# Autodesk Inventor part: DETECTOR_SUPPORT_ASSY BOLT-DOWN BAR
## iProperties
Shininess: 64.0
Length Units: 11272
Angle Units: 11279
Time Units: 11290
Mass Units: 11286
Length Display Precision: 3
Angle Display Precision: 2
Compacted: True
Part Number: DETECTOR_SUPPORT_ASSY BOLT-DOWN BAR
Document SubType Name: Modeling
Created: 2004-08
Designer: John Blackburn
Material: ALUMINUM
Manufacturer: Standard
Standards Organization: Custom
Density: 0.0
Volumn: 0.0
Area: 0.0
PropertySet Name: Model Information
Control State: 0
Master: False
Checked Out: False
Author: John Blackburn
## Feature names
1. ExtrusionBlind1
2. AM_HOLE_0301DE_1 [Hole]
3. Hole1
4. ExtrusionThru1
5. Chamfer1
